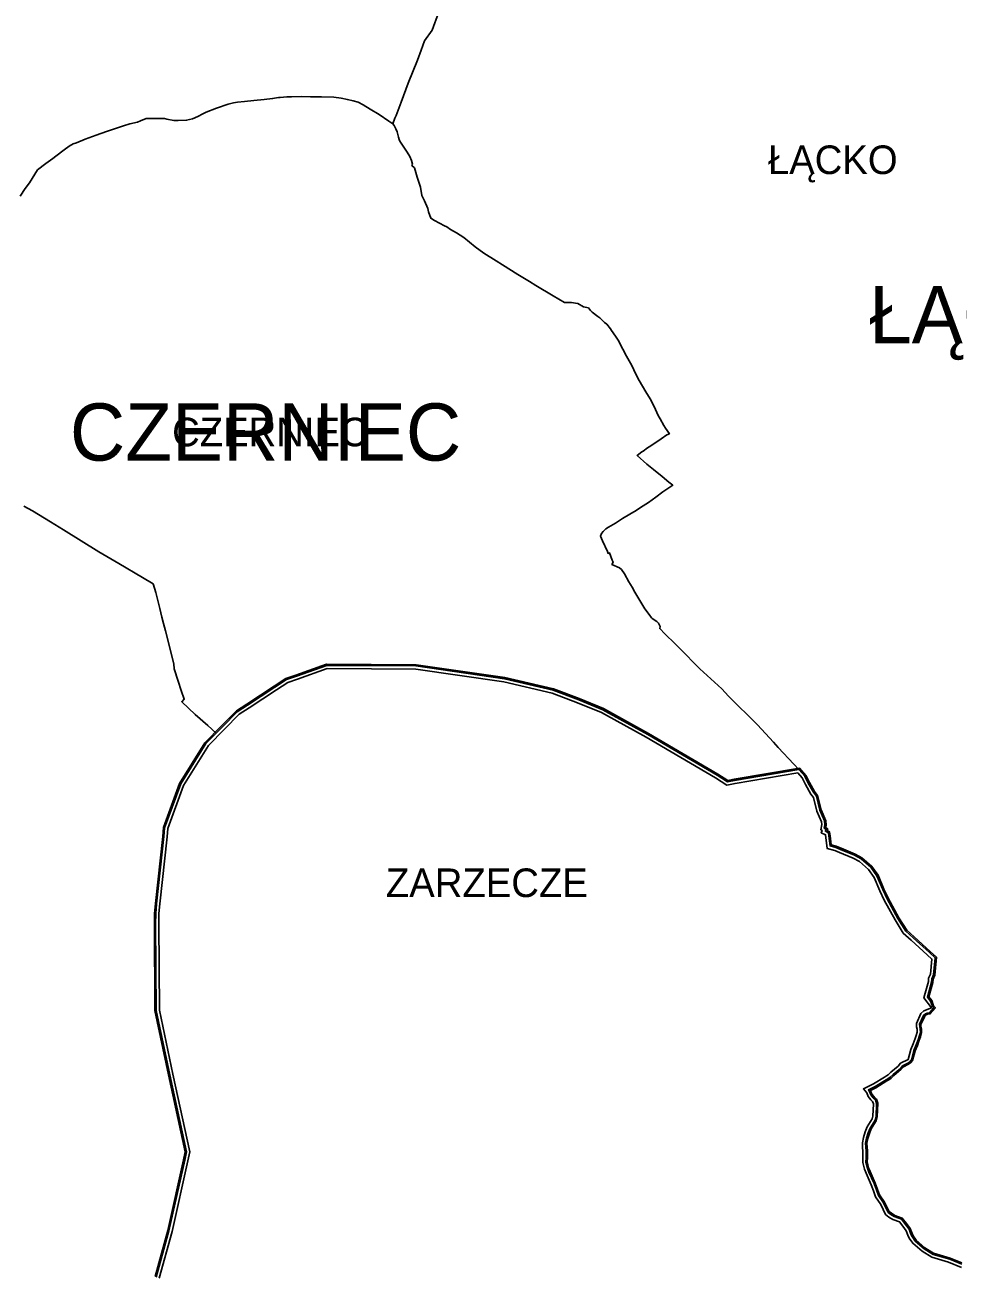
# Model space of a CAD drawing. Extents: x -562952 to -547638, y 190691 to 208158.
# Drawn here: x -559633 to -556696, y 198378 to 202309 of the extents above; entities that cross this region are included whole.
import ezdxf

# ---------------------------------------------------------------- set-up
doc = ezdxf.new("R2010")
doc.units = 0
for name, color, linetype in [('granica A_B', 7, 'Continuous'), ('granica_sołectwa', 7, 'Continuous'), ('nazwy miejscowości', 7, 'Continuous'), ('nazwy miejscowości DUŻE', 7, 'Continuous')]:
    doc.layers.add(name, color=color, linetype=linetype)

msp = doc.modelspace()

# ---------------------------------------------------------------- linework, layer by layer
at = {"layer": 'granica A_B'}
for points in [[(-559223.6, 198372.7), (-559184, 198517.3), (-559134.2, 198740), (-559128.7, 198765.2), (-559181.1, 199006.6), (-559224.2, 199209.3), (-559226, 199481.7), (-559225.6, 199515), (-559222.8, 199545.8), (-559199.8, 199756.6), (-559197.7, 199785.1), (-559146.8, 199923.7), (-559066.8, 200051.2), (-559014.9, 200104.6), (-558968, 200151.8), (-558935.4, 200173), (-558849.3, 200229.7), (-558812.5, 200253.9), (-558780.8, 200264.5), (-558684.7, 200298.5), (-558403, 200297), (-558124, 200256.6), (-557970.8, 200221.2), (-557889.9, 200190.5), (-557813.5, 200159.1), (-557803.9, 200153.7), (-557672.2, 200081.1), (-557454.6, 199952.8), (-557422.8, 199933), (-557402.6, 199937.1), (-557197.7, 199971.8), (-557177.3, 199948.8), (-557166, 199926.4), (-557150.3, 199897.9), (-557140.2, 199885.6), (-557129.5, 199840.7), (-557114.3, 199806.4), (-557113.2, 199793.5), (-557115, 199784.7), (-557108.2, 199780.2), (-557110.5, 199775.1), (-557103, 199771.4), (-557101.1, 199759.2), (-557097.5, 199730.2), (-557082.1, 199726), (-557066.4, 199719.5), (-557022.7, 199701.1), (-557001.2, 199689.2), (-556969.8, 199662.8), (-556950.1, 199634.8), (-556931.6, 199591.1), (-556918.5, 199562.9), (-556884.5, 199501.2), (-556860, 199461.8), (-556836.7, 199441.2), (-556786, 199394.5), (-556766.4, 199376.8), (-556772.1, 199320.2), (-556777.4, 199307.8), (-556778.2, 199298), (-556790.5, 199252.3), (-556781.6, 199240.4), (-556775.7, 199224.3), (-556769.9, 199217.4), (-556786.1, 199198.6), (-556795.2, 199197.4), (-556798.9, 199195.9), (-556803.7, 199191.3), (-556815.6, 199165.3), (-556815.4, 199159.8), (-556813.8, 199152), (-556813.2, 199139.5), (-556816.7, 199126.5), (-556820.5, 199116.1), (-556826.7, 199099.6), (-556833.7, 199082.6), (-556841.9, 199052), (-556848.2, 199044.5), (-556854.3, 199040.2), (-556870.6, 199032.1), (-556877.3, 199024.6), (-556900.4, 199005.3), (-556909.4, 198996.6), (-556916.2, 198991.7), (-556922.8, 198987.9), (-556957.4, 198966.4), (-556974.4, 198958), (-556973.6, 198957.1), (-556969.6, 198946.1), (-556962.4, 198937.8), (-556955, 198930.8), (-556950.7, 198917.5), (-556952.7, 198874.5), (-556955.9, 198862.4), (-556971.9, 198837.6), (-556977.7, 198823), (-556982.4, 198806.6), (-556985.3, 198791.9), (-556984.7, 198779.5), (-556983.7, 198767.8), (-556983.7, 198747), (-556984.2, 198733.2), (-556979.8, 198715.1), (-556975.1, 198702.7), (-556958.9, 198666.5), (-556951.8, 198646.7), (-556945.5, 198629.9), (-556929.7, 198606.3), (-556915.4, 198577), (-556908.3, 198571.6), (-556897.4, 198565.1), (-556874, 198556.5), (-556860.9, 198539.3), (-556849.2, 198523.5), (-556843.4, 198508), (-556839.9, 198500.9), (-556830.5, 198486.9), (-556803, 198463.4), (-556775.7, 198446.1), (-556723.7, 198430.8), (-556686.8, 198415.7)], [(-559210.6, 198367.2), (-559170.4, 198514), (-559120.5, 198737), (-559114.4, 198765.2), (-559167.4, 199009.5), (-559210.2, 199210.9), (-559212, 199481.6), (-559211.7, 199514.3), (-559208.9, 199544.4), (-559185.9, 199755.3), (-559183.9, 199782.1), (-559134.2, 199917.5), (-559055.7, 200042.5), (-559005, 200094.7), (-558959.1, 200140.9), (-558927.7, 200161.3), (-558841.6, 200218), (-558806.3, 200241.2), (-558776.3, 200251.3), (-558682.3, 200284.5), (-558404, 200283), (-558126.6, 200242.8), (-557974.8, 200207.7), (-557895.1, 200177.5), (-557819.6, 200146.5), (-557810.7, 200141.4), (-557679.1, 200069), (-557461.9, 199940.8), (-557425.5, 199918.2), (-557400, 199923.4), (-557203, 199956.7), (-557189, 199940.9), (-557178.4, 199919.9), (-557161.9, 199890), (-557153.1, 199879.2), (-557142.8, 199836.2), (-557128, 199802.9), (-557127.3, 199794.3), (-557130.7, 199778.1), (-557125.9, 199775), (-557128.8, 199768.5), (-557115.5, 199761.9), (-557110.3, 199719.2), (-557086.7, 199712.7), (-557071.8, 199706.6), (-557028.9, 199688.5), (-557009.1, 199677.6), (-556980.2, 199653.3), (-556962.4, 199627.9), (-556944.4, 199585.4), (-556931, 199556.6), (-556896.6, 199494.1), (-556870.8, 199452.7), (-556846.1, 199430.8), (-556795.4, 199384.2), (-556781, 199371.2), (-556785.8, 199323.8), (-556791.2, 199311.3), (-556792.1, 199300.4), (-556805.8, 199249.4), (-556781.9, 199217.6), (-556806.5, 199208), (-556815.3, 199199.6), (-556829.8, 199168.1), (-556829.4, 199158.1), (-556827.7, 199150.2), (-556827.3, 199141), (-556830, 199130.8), (-556833.6, 199121), (-556839.8, 199104.7), (-556847, 199087.1), (-556855.6, 199055.2), (-556879.3, 199043.4), (-556887.1, 199034.7), (-556909.7, 199015.7), (-556918.3, 199007.4), (-556923.8, 199003.5), (-556930, 198999.9), (-556964.2, 198978.6), (-556996.3, 198962.8), (-556986, 198950), (-556981.8, 198938.8), (-556972.5, 198928.2), (-556967.3, 198923.1), (-556964.8, 198915.6), (-556966.6, 198876.7), (-556968.9, 198868.2), (-556984.5, 198844), (-556990.9, 198827.5), (-556996, 198809.9), (-556999.3, 198792.9), (-556998.7, 198778.6), (-556997.7, 198767.2), (-556997.7, 198747.3), (-556998.2, 198731.8), (-556993.2, 198710.9), (-556988, 198697.4), (-556971.9, 198661.3), (-556965, 198641.9), (-556958, 198623.5), (-556941.9, 198599.3), (-556926.5, 198567.8), (-556916.1, 198559.9), (-556903.5, 198552.4), (-556882.7, 198544.7), (-556872.1, 198530.9), (-556861.7, 198516.7), (-556856.3, 198502.4), (-556852, 198493.8), (-556841, 198477.5), (-556811.4, 198452.1), (-556781.5, 198433.2), (-556728.3, 198417.5), (-556688.4, 198401.3)]]:
    msp.add_lwpolyline(points, dxfattribs=at)
at = {"layer": 'granica_sołectwa'}
msp.add_line((-559058.3, 200106.1), (-559031.7, 200081.6), dxfattribs=at)
for points in [[(-558332.3, 202346.9), (-558352.7, 202293.1), (-558376.3, 202259.3), (-558386.5, 202229.5), (-558398.4, 202198.1), (-558428, 202126.1), (-558450.4, 202066.2), (-558465.4, 202023.9), (-558469.5, 202016.1), (-558475.8, 201997.8), (-558488.7, 202005.9), (-558518.8, 202027.2), (-558546.9, 202044.2), (-558569.3, 202057.7), (-558585.5, 202065.8), (-558601.3, 202070.3), (-558619, 202074.2), (-558638.9, 202079.2), (-558661.9, 202081.9), (-558700.5, 202083.4), (-558735.5, 202083.4), (-558764.7, 202084.3), (-558795.2, 202083.1), (-558809.6, 202082.5), (-558829.9, 202081.3), (-558835.6, 202081), (-558842.2, 202079.5), (-558854.1, 202077.4), (-558880.4, 202074.8), (-558913.3, 202071.8), (-558942, 202068.2), (-558964.3, 202066.4), (-558977.2, 202063.7), (-558994.2, 202059.8), (-559030.1, 202046.9), (-559063.3, 202035), (-559073.7, 202029.9), (-559089.2, 202021.2), (-559106.3, 202014), (-559124.8, 202009.2), (-559151.4, 202008), (-559164.6, 202008.9), (-559187, 202012.8), (-559194.5, 202014.6), (-559232, 202015.2), (-559252.1, 202014.6), (-559269.1, 202007.4), (-559278.9, 202003.2)], [(-559278.9, 202003.2), (-559302.6, 201998.4), (-559323.2, 201992.2), (-559338.7, 201986.2), (-559376.4, 201973.9), (-559408.7, 201962.5), (-559443.6, 201950.1), (-559470.3, 201938.7), (-559481.6, 201934.8), (-559493.6, 201927.3), (-559509.1, 201916.5), (-559535.6, 201896.3), (-559545.5, 201888.8), (-559567, 201873.6), (-559593.7, 201853.2), (-559618.2, 201812.5), (-559632.5, 201795), (-559648.3, 201770.8)], [(-558475.8, 201997.8), (-558471.6, 201992.3), (-558466.4, 201982.4), (-558462.2, 201972.4), (-558457.9, 201956.3), (-558456, 201949), (-558453.9, 201943.8), (-558448, 201933.6), (-558431.2, 201908.5), (-558422.4, 201895.7), (-558417.2, 201882.9), (-558414.6, 201870.8), (-558416.5, 201867), (-558407.5, 201859.2), (-558399.7, 201830.1), (-558388.6, 201798.3), (-558384.5, 201772.6), (-558376.2, 201755.6), (-558366.5, 201731.7), (-558363.9, 201721.7), (-558356.4, 201700.8), (-558344.8, 201694.1), (-558313.1, 201677.6), (-558306.2, 201674), (-558295.1, 201666.2), (-558276.4, 201655.3), (-558252.9, 201640.3), (-558216.9, 201611.2), (-558189.7, 201591.7), (-558151.6, 201566.9), (-558131.3, 201554.6), (-558083.3, 201524.6), (-558046.1, 201501.7), (-558026.9, 201489.9), (-557972.2, 201457), (-557936.7, 201435.7), (-557915, 201436.4), (-557894.8, 201432.8), (-557876.6, 201422.9), (-557860.8, 201419.6), (-557854.1, 201411.1), (-557848.9, 201405.9), (-557831.3, 201391.6), (-557824.7, 201388.1), (-557810, 201373.6), (-557803.6, 201367.7), (-557791.6, 201353.7), (-557788.5, 201348.3), (-557776, 201330.5), (-557767.4, 201317.3), (-557752.8, 201289.1), (-557740.9, 201266.9), (-557724.4, 201238), (-557712.1, 201210.7), (-557701.5, 201190.6), (-557680.9, 201155.1), (-557666.9, 201132.8), (-557654.4, 201109), (-557641.4, 201081), (-557635.7, 201070.4), (-557624.2, 201049.1), (-557618.9, 201041), (-557606.6, 201023.3), (-557614, 201019.5), (-557632.7, 201007.4), (-557665.1, 200985.1), (-557674.8, 200978.5), (-557689.2, 200968.6), (-557692.8, 200966.3)], [(-557677.4, 200927.8), (-557656.4, 200910.9), (-557629, 200888.7), (-557607.8, 200871.3), (-557596.1, 200861.2), (-557626.9, 200840.4), (-557648.8, 200823.4), (-557672.4, 200807.6), (-557696.8, 200791.2), (-557711.2, 200782.2), (-557731.2, 200770.1), (-557753.5, 200756.5), (-557776.4, 200742.3), (-557798.1, 200729.3), (-557806.8, 200723.8), (-557814.8, 200715.9), (-557819.9, 200709.7), (-557822.7, 200701.2), (-557817, 200686.5), (-557801.2, 200652.9), (-557799.1, 200646.8), (-557794.6, 200648.5), (-557785.9, 200625.7), (-557783.2, 200619.9), (-557787, 200612.2), (-557763, 200601.4), (-557757.5, 200596.7), (-557747.3, 200582.9), (-557733.5, 200558.1), (-557723.5, 200541.1), (-557714.6, 200525.1), (-557705.8, 200509.8), (-557683.4, 200473), (-557670.4, 200454.5), (-557662.3, 200444.5), (-557660.4, 200441.9), (-557646.4, 200433), (-557640.2, 200427.9), (-557635.6, 200417.2), (-557636.7, 200410.6), (-557620.3, 200394.4), (-557588, 200362.1), (-557574.9, 200348.9), (-557510.4, 200283.8), (-557441.4, 200221.4), (-557420.6, 200198.2), (-557329.5, 200108.1), (-557279.3, 200053.1), (-557264.5, 200036.4), (-557214.9, 199983.7), (-557199.4, 199967.8), (-557180.6, 199946.6), (-557169.6, 199924.5), (-557153.6, 199895.6), (-557143.9, 199883.7), (-557133.3, 199839.4), (-557118.2, 199805.4), (-557117.3, 199793.7), (-557119.5, 199782.8)], [(-557692.8, 200966.3), (-557708.2, 200954.8), (-557677.4, 200927.8)], [(-559636.1, 200795.9), (-559608.9, 200780.4), (-559552.5, 200745.8), (-559511.7, 200720.8), (-559455.7, 200686.3), (-559400.2, 200652.3), (-559337.5, 200614.9), (-559263, 200570.7), (-559230, 200551), (-559221.7, 200524), (-559209.1, 200474), (-559202.3, 200446.6), (-559197.3, 200426.5), (-559190.9, 200403.7), (-559164.7, 200300), (-559164, 200283.7), (-559151.1, 200244.8), (-559141.5, 200215.3), (-559131.8, 200188.7), (-559140, 200180.5), (-559097.6, 200140.8), (-559058.3, 200106.1)], [(-557199.2, 199967.5), (-557401.9, 199933.2), (-557423.6, 199928.8), (-557456.7, 199949.4), (-557674.2, 200077.7), (-557805.8, 200150.2), (-557815.3, 200155.5), (-557891.4, 200186.8), (-557971.9, 200217.3), (-558124.8, 200252.7), (-558403.3, 200293), (-558684, 200294.5), (-558779.5, 200260.7), (-558810.7, 200250.2), (-558847.1, 200226.4), (-558933.2, 200169.7), (-558965.4, 200148.7), (-559012.1, 200101.8), (-559063.6, 200048.7), (-559143.2, 199921.9), (-559193.7, 199784.2), (-559195.8, 199756.3)], [(-559195.8, 199756.3), (-559218.8, 199545.4), (-559221.7, 199514.8), (-559222, 199481.7), (-559220.2, 199209.8), (-559177.2, 199007.4), (-559124.6, 198765.2), (-559130.3, 198739.2), (-559180.1, 198516.4), (-559219.9, 198371.1)], [(-557119.5, 199782.8), (-557113.2, 199778.7), (-557115.7, 199773.2), (-557106.6, 199768.7), (-557105, 199758.7), (-557101.2, 199727.1), (-557083.4, 199722.2), (-557067.9, 199715.9), (-557024.5, 199697.5), (-557003.4, 199685.9), (-556972.8, 199660.1), (-556953.6, 199632.8), (-556935.3, 199589.5), (-556922.1, 199561.1), (-556887.9, 199499.1), (-556863.1, 199459.2), (-556839.4, 199438.2), (-556788.6, 199391.6), (-556770.6, 199375.2), (-556776, 199321.2), (-556781.4, 199308.8), (-556782.2, 199298.7), (-556794.9, 199251.5), (-556785.1, 199238.5), (-556779.2, 199222.3), (-556775.2, 199217.5), (-556788.1, 199202.3), (-556796.2, 199201.3), (-556801.1, 199199.4), (-556807, 199193.7), (-556819.7, 199166.1), (-556819.4, 199159.3), (-556817.8, 199151.5), (-556817.2, 199139.9), (-556820.5, 199127.7), (-556824.3, 199117.5), (-556830.5, 199101), (-556837.5, 199083.9), (-556845.6, 199053.9), (-556851, 199047.4), (-556856.4, 199043.7), (-556865, 199039.3), (-556873.1, 199035.3), (-556880.1, 199027.5), (-556903, 199008.3), (-556911.9, 198999.7), (-556918.4, 198995.1), (-556924.9, 198991.3), (-556959.3, 198969.9), (-556980.6, 198959.4), (-556977.1, 198955), (-556973.1, 198944)], [(-556973.1, 198944), (-556965.3, 198935.1), (-556958.5, 198928.6), (-556954.7, 198917), (-556956.6, 198875.2), (-556959.6, 198864.1), (-556975.5, 198839.4), (-556981.5, 198824.3), (-556986.3, 198807.6), (-556989.3, 198792.2), (-556988.7, 198779.2), (-556987.7, 198767.6), (-556987.7, 198747.1), (-556988.2, 198732.8), (-556983.6, 198713.9), (-556978.8, 198701.2), (-556962.6, 198665), (-556955.6, 198645.3), (-556949.1, 198628.1), (-556933.2, 198604.3), (-556918.6, 198574.3), (-556910.5, 198568.2), (-556899.2, 198561.5), (-556876.5, 198553.1), (-556864.1, 198536.9), (-556852.8, 198521.5), (-556847.1, 198506.4), (-556843.3, 198498.9), (-556833.5, 198484.2), (-556805.4, 198460.2), (-556777.4, 198442.4), (-556725, 198427), (-556687.3, 198411.6)]]:
    msp.add_lwpolyline(points, dxfattribs=at)

# ---------------------------------------------------------------- texts
at = {"layer": 'nazwy miejscowości'}
for s, p in [('ŁĄCKO', (-557296.7, 201840)), ('CZERNIEC', (-559170.1, 200983.8)), ('ZARZECZE', (-558498, 199566.1))]:
    msp.add_text(s, height=90, dxfattribs=at).set_placement(p)
at = {"layer": 'nazwy miejscowości DUŻE'}
for s, p in [('ŁĄCKO', (-556978.3, 201307.8)), ('CZERNIEC', (-559491.5, 200938.8))]:
    msp.add_text(s, height=180, dxfattribs=at).set_placement(p)

doc.saveas('drawing.dxf')
